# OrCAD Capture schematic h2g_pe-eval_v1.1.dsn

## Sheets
1 Interface-Power: size C; title: H2G PE-Eval PCB; rev: 1.1; company: University of Arkansas (NCREPT); note: 700 W. Research Center Blvd; note: Fayetteville, AR 72701
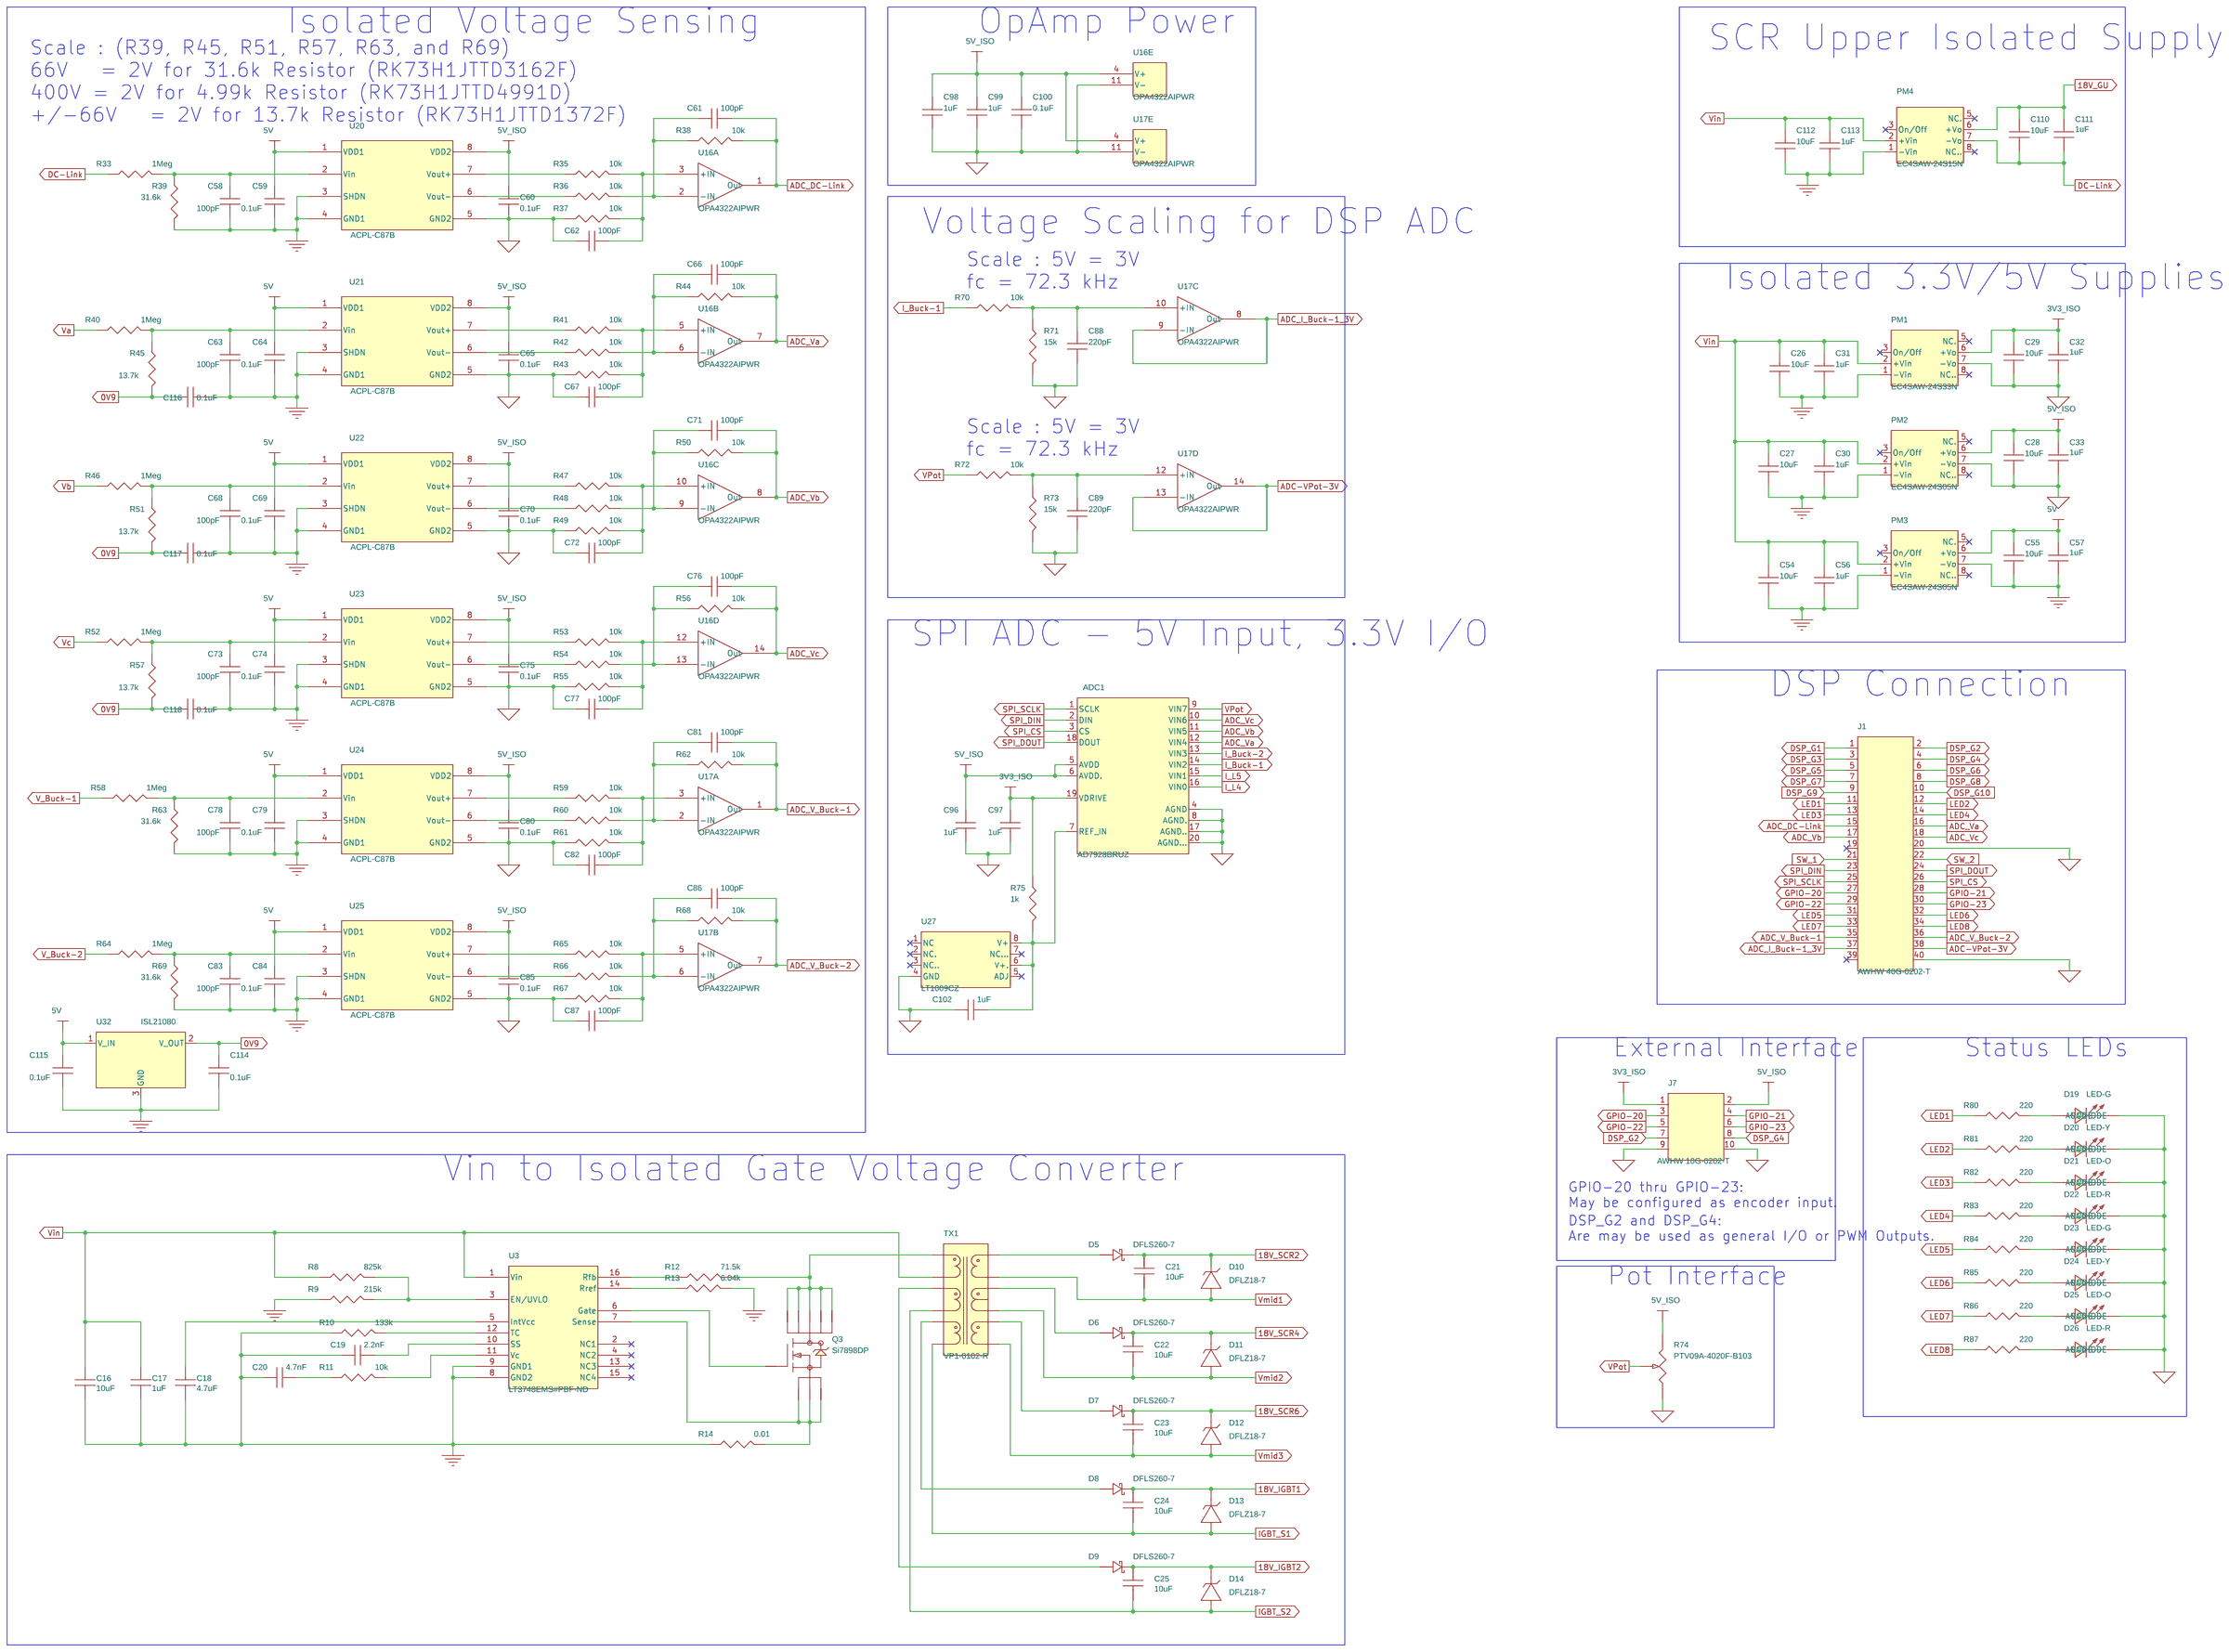
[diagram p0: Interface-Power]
2 Converters: size C
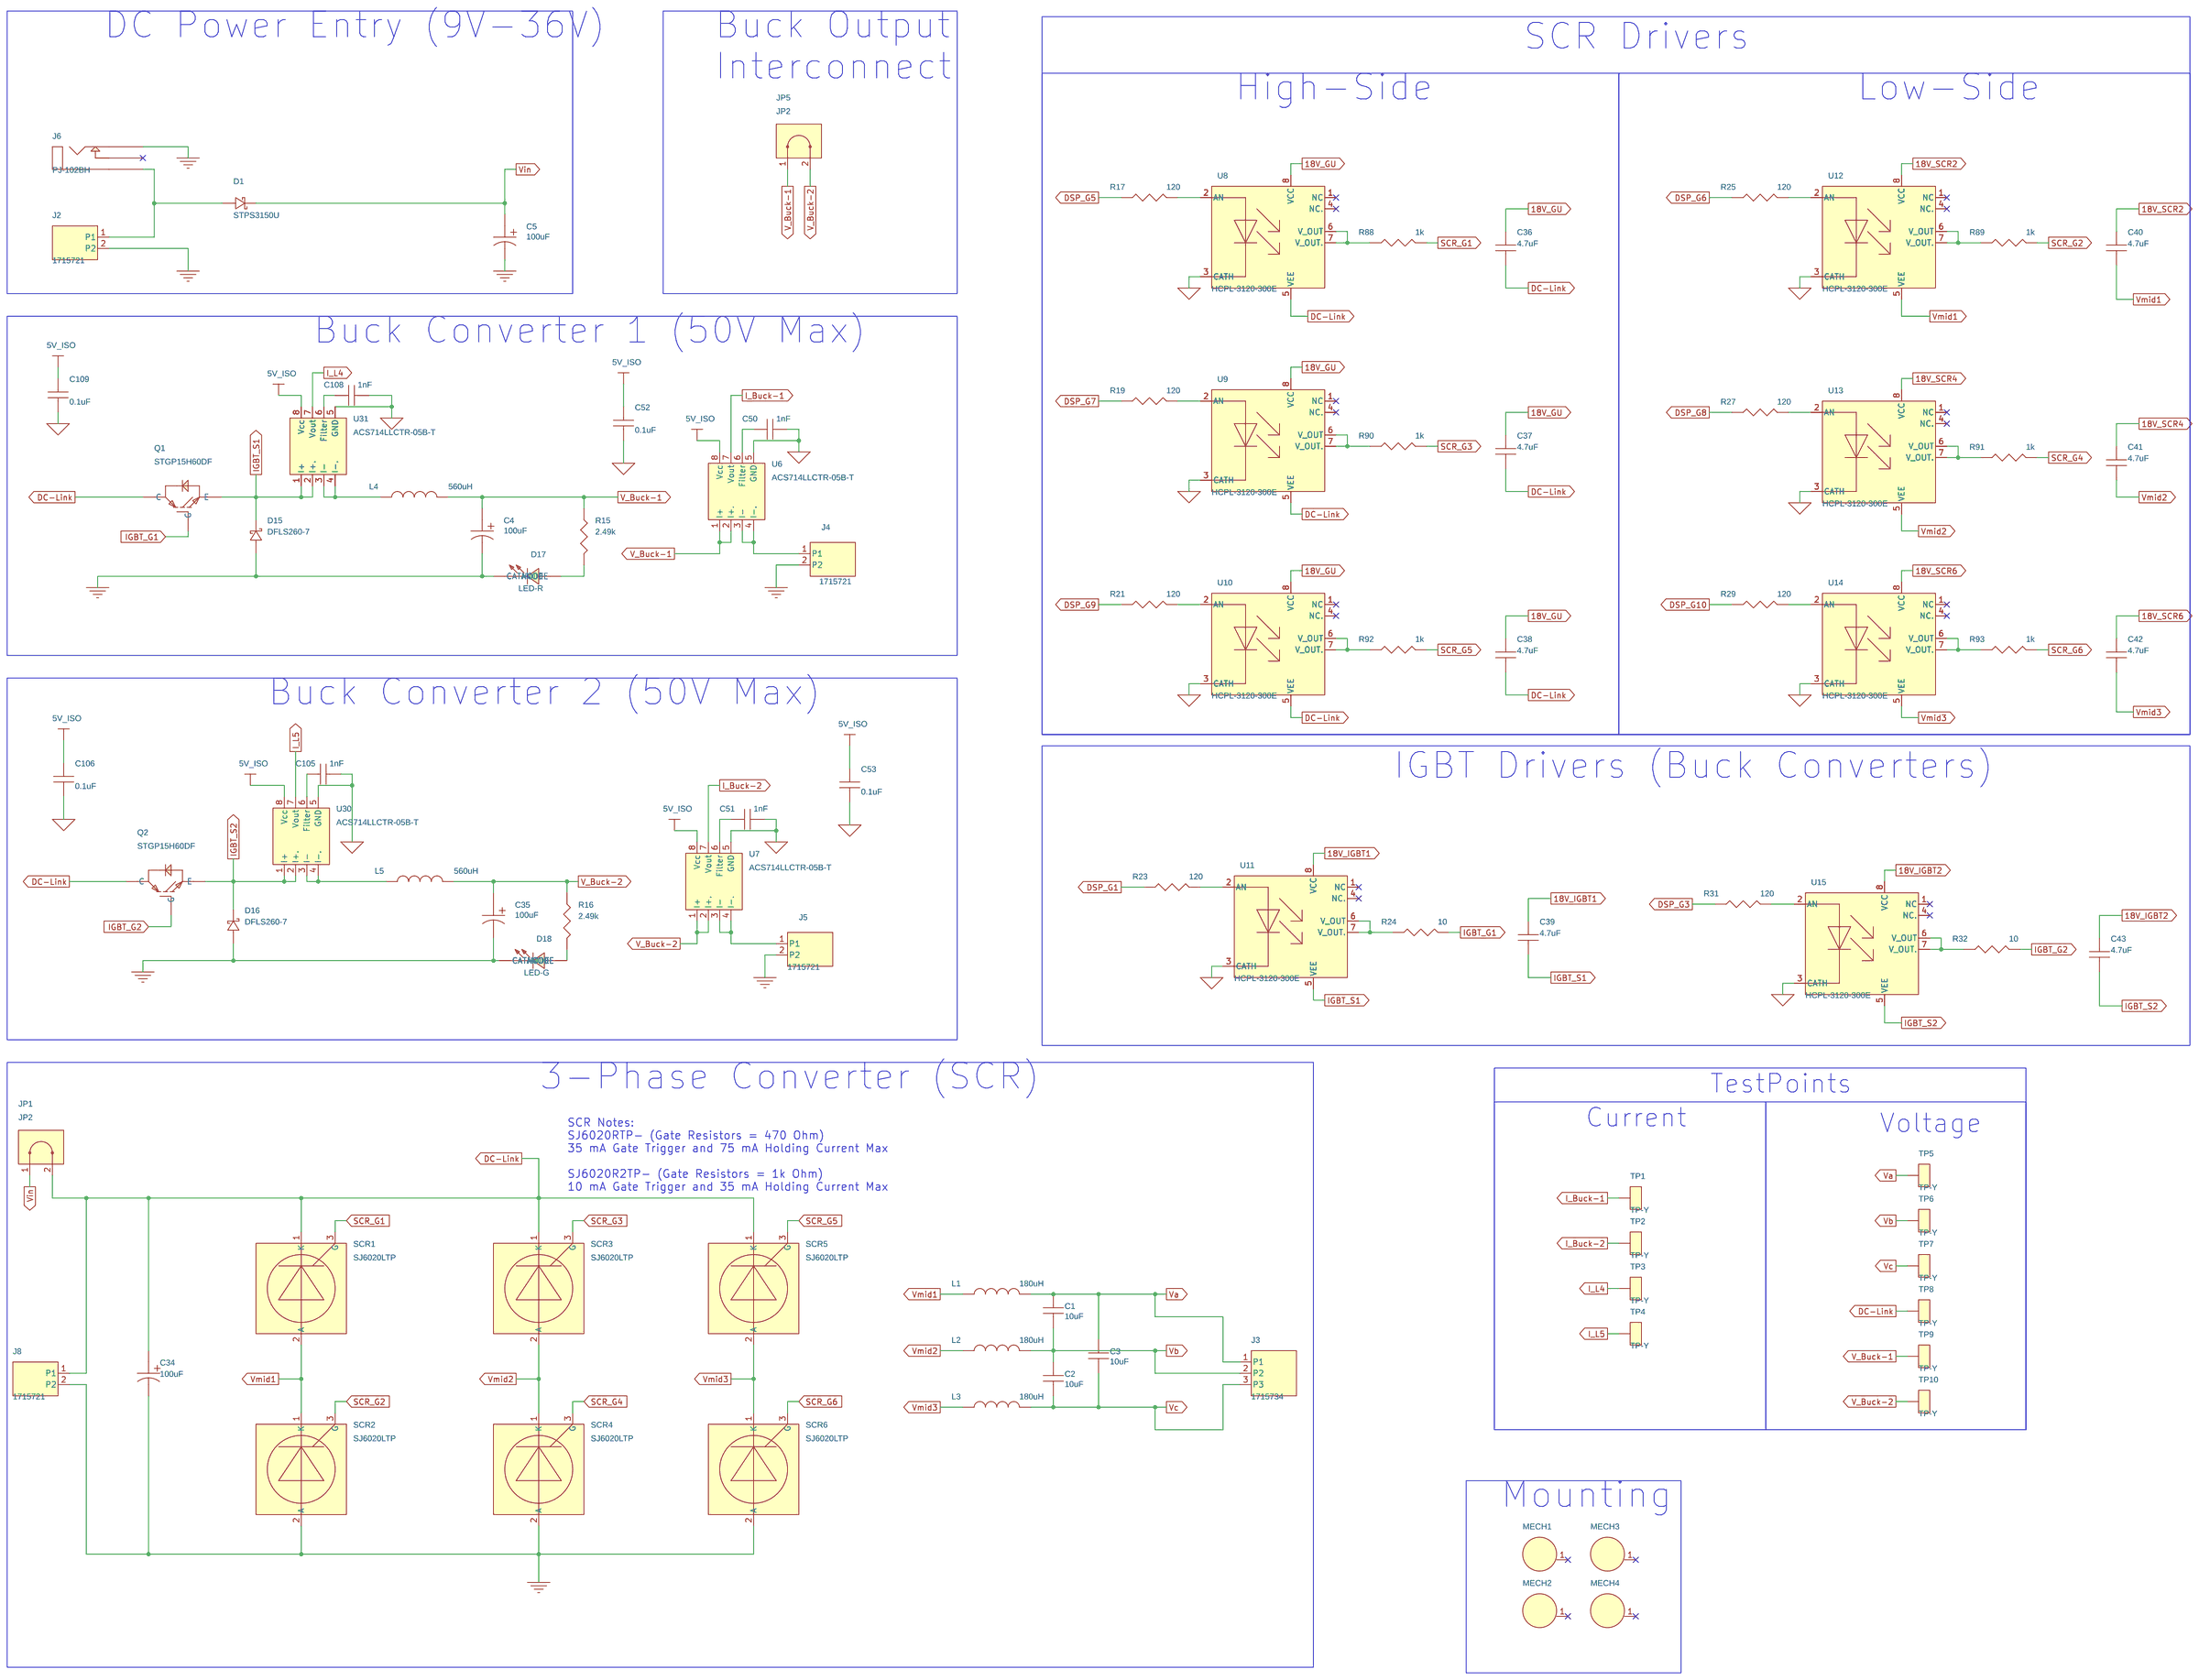
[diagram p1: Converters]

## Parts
sheet Converters
C1  10uF  [ECQ-E2106KFB]
C2  10uF  [ECQ-E2106KFB]
C3  10uF  [ECQ-E2106KFB]
C4  100uF  [UVZ1H101MPD]
C5  100uF  [UVZ1H101MPD]
C34  100uF  [UVZ1H101MPD]
C35  100uF  [UVZ1H101MPD]
C36  4.7uF  [C_1206]
C37  4.7uF  [C_1206]
C38  4.7uF  [C_1206]
C39  4.7uF  [C_1206]
C40  4.7uF  [C_1206]
C41  4.7uF  [C_1206]
C42  4.7uF  [C_1206]
C43  4.7uF  [C_1206]
C50  1nF  [C_0603]
C51  1nF  [C_0603]
C52  0.1uF  [C_0603]
C53  0.1uF  [C_0603]
C105  1nF  [C_0603]
C106  0.1uF  [C_0603]
C108  1nF  [C_0603]
C109  0.1uF  [C_0603]
D1  STPS3150U  [DO-214AA_SMB]
D15  DFLS260-7  [PowerDI-123]
D16  DFLS260-7  [PowerDI-123]
D17  LED-R  [LED_0805-RED]
D18  LED-G  [LED_0805-GREEN]
J2  1715721  [1715721]
J3  1715734  [1715734]
J4  1715721  [1715721]
J5  1715721  [1715721]
J6  PJ-102BH  [DC-PWR_JACK]
J8  1715721  [1715721]
JP1  JP2  [J_1X2]
JP5  JP2  [J_1X2]
L1  180uH  [PCV-2-184-05L]
L2  180uH  [PCV-2-184-05L]
L3  180uH  [PCV-2-184-05L]
L4  560uH  [PCV-2-564-02L]
L5  560uH  [PCV-2-564-02L]
MECH1  Mech_Hole  [4-40_SCREW]
MECH2  Mech_Hole  [4-40_SCREW]
MECH3  Mech_Hole  [4-40_SCREW]
MECH4  Mech_Hole  [4-40_SCREW]
Q1  STGP15H60DF  [TO-220]
Q2  STGP15H60DF  [TO-220]
R15  2.49k  [R_2512]
R16  2.49k  [R_2512]
R17  120  [R_1206]
R19  120  [R_1206]
R21  120  [R_1206]
R23  120  [R_1206]
R24  10  [R_1206]
R25  120  [R_1206]
R27  120  [R_1206]
R29  120  [R_1206]
R31  120  [R_1206]
R32  10  [R_1206]
R88  1k  [R_0805]
R89  1k  [R_0805]
R90  1k  [R_0805]
R91  1k  [R_0805]
R92  1k  [R_0805]
R93  1k  [R_0805]
SCR1  SJ6020LTP  [TO-220]
SCR2  SJ6020LTP  [TO-220]
SCR3  SJ6020LTP  [TO-220]
SCR4  SJ6020LTP  [TO-220]
SCR5  SJ6020LTP  [TO-220]
SCR6  SJ6020LTP  [TO-220]
TP1  TP-Y  [TP-YELLOW]
TP2  TP-Y  [TP-YELLOW]
TP3  TP-Y  [TP-YELLOW]
TP4  TP-Y  [TP-YELLOW]
TP5  TP-Y  [TP-YELLOW]
TP6  TP-Y  [TP-YELLOW]
TP7  TP-Y  [TP-YELLOW]
TP8  TP-Y  [TP-YELLOW]
TP9  TP-Y  [TP-YELLOW]
TP10  TP-Y  [TP-YELLOW]
U6  ACS714LLCTR-05B-T  [8-SOIC]
U7  ACS714LLCTR-05B-T  [8-SOIC]
U8  HCPL-3120-300E  [8-DIP_GW]
U9  HCPL-3120-300E  [8-DIP_GW]
U10  HCPL-3120-300E  [8-DIP_GW]
U11  HCPL-3120-300E  [8-DIP_GW]
U12  HCPL-3120-300E  [8-DIP_GW]
U13  HCPL-3120-300E  [8-DIP_GW]
U14  HCPL-3120-300E  [8-DIP_GW]
U15  HCPL-3120-300E  [8-DIP_GW]
U30  ACS714LLCTR-05B-T  [8-SOIC]
U31  ACS714LLCTR-05B-T  [8-SOIC]
sheet Interface-Power
ADC1  AD7928BRUZ  [20-TSSOP]
C16  10uF  [C_1206]
C17  1uF  [C_0603]
C18  4.7uF  [C_1206]
C19  2.2nF  [C_0603]
C20  4.7nF  [C_0603]
C21  10uF  [C_1206]
C22  10uF  [C_1206]
C23  10uF  [C_1206]
C24  10uF  [C_1206]
C25  10uF  [C_1206]
C26  10uF  [C_1206]
C27  10uF  [C_1206]
C28  10uF  [C_1206]
C29  10uF  [C_1206]
C30  1uF  [C_0603]
C31  1uF  [C_0603]
C32  1uF  [C_0603]
C33  1uF  [C_0603]
C54  10uF  [C_1206]
C55  10uF  [C_1206]
C56  1uF  [C_0603]
C57  1uF  [C_0603]
C58  100pF  [C_0603]
C59  0.1uF  [C_0603]
C60  0.1uF  [C_0603]
C61  100pF  [C_0603]
C62  100pF  [C_0603]
C63  100pF  [C_0603]
C64  0.1uF  [C_0603]
C65  0.1uF  [C_0603]
C66  100pF  [C_0603]
C67  100pF  [C_0603]
C68  100pF  [C_0603]
C69  0.1uF  [C_0603]
C70  0.1uF  [C_0603]
C71  100pF  [C_0603]
C72  100pF  [C_0603]
C73  100pF  [C_0603]
C74  0.1uF  [C_0603]
C75  0.1uF  [C_0603]
C76  100pF  [C_0603]
C77  100pF  [C_0603]
C78  100pF  [C_0603]
C79  0.1uF  [C_0603]
C80  0.1uF  [C_0603]
C81  100pF  [C_0603]
C82  100pF  [C_0603]
C83  100pF  [C_0603]
C84  0.1uF  [C_0603]
C85  0.1uF  [C_0603]
C86  100pF  [C_0603]
C87  100pF  [C_0603]
C88  220pF  [C_0603]
C89  220pF  [C_0603]
C96  1uF  [C_0603]
C97  1uF  [C_0603]
C98  1uF  [C_0603]
C99  1uF  [C_0603]
C100  0.1uF  [C_0603]
C102  1uF  [C_0603]
C110  10uF  [C_1206]
C111  1uF  [C_0603]
C112  10uF  [C_1206]
C113  1uF  [C_0603]
C114  0.1uF  [C_0603]
C115  0.1uF  [C_0603]
C116  0.1uF  [C_0603]
C117  0.1uF  [C_0603]
C118  0.1uF  [C_0603]
D5  DFLS260-7  [PowerDI-123]
D6  DFLS260-7  [PowerDI-123]
D7  DFLS260-7  [PowerDI-123]
D8  DFLS260-7  [PowerDI-123]
D9  DFLS260-7  [PowerDI-123]
D10  DFLZ18-7  [PowerDI-123]
D11  DFLZ18-7  [PowerDI-123]
D12  DFLZ18-7  [PowerDI-123]
D13  DFLZ18-7  [PowerDI-123]
D14  DFLZ18-7  [PowerDI-123]
D19  LED-G  [LED_0805-GREEN]
D20  LED-Y  [LED_0805-YELLOW]
D21  LED-O  [LED_0805-ORANGE]
D22  LED-R  [LED_0805-RED]
D23  LED-G  [LED_0805-GREEN]
D24  LED-Y  [LED_0805-YELLOW]
D25  LED-O  [LED_0805-ORANGE]
D26  LED-R  [LED_0805-RED]
J1  AWHW 40G-0202-T  [40-IDC-M]
J7  AWHW 10G-0202-T  [10-IDC-M]
PM1  EC4SAW-24S33N  [SIP-8]
PM2  EC4SAW-24S05N  [SIP-8]
PM3  EC4SAW-24S05N  [SIP-8]
PM4  EC4SAW-24S15N  [SIP-8]
Q3  Si7898DP  [SO-8_PP]
R8  825k  [R_0603]
R9  215k  [R_0603]
R10  133k  [R_0603]
R11  10k  [R_0603]
R12  71.5k  [R_0603]
R13  6.04k  [R_0603]
R14  0.01  [R_1206]
R33  1Meg  [R_1206]
R35  10k  [R_0603]
R36  10k  [R_0603]
R37  10k  [R_0603]
R38  10k  [R_0603]
R39  31.6k  [R_0805]
R40  1Meg  [R_1206]
R41  10k  [R_0603]
R42  10k  [R_0603]
R43  10k  [R_0603]
R44  10k  [R_0603]
R45  13.7k  [R_0603]
R46  1Meg  [R_1206]
R47  10k  [R_0603]
R48  10k  [R_0603]
R49  10k  [R_0603]
R50  10k  [R_0603]
R51  13.7k  [R_0603]
R52  1Meg  [R_1206]
R53  10k  [R_0603]
R54  10k  [R_0603]
R55  10k  [R_0603]
R56  10k  [R_0603]
R57  13.7k  [R_0603]
R58  1Meg  [R_1206]
R59  10k  [R_0603]
R60  10k  [R_0603]
R61  10k  [R_0603]
R62  10k  [R_0603]
R63  31.6k  [R_0805]
R64  1Meg  [R_1206]
R65  10k  [R_0603]
R66  10k  [R_0603]
R67  10k  [R_0603]
R68  10k  [R_0603]
R69  31.6k  [R_0805]
R70  10k  [R_0603]
R71  15k  [R_0603]
R72  10k  [R_0603]
R73  15k  [R_0603]
R74  PTV09A-4020F-B103  [9MM_POT]
R75  1k  [R_0805]
R80  220  [R_0805]
R81  220  [R_0805]
R82  220  [R_0805]
R83  220  [R_0805]
R84  220  [R_0805]
R85  220  [R_0805]
R86  220  [R_0805]
R87  220  [R_0805]
TX1  VP1-0102-R  [TX-VP1]
U3  LT3748EMS#PBF-ND  [16-MSOP]
U16  OPA4322AIPWR  [OPA4332_14-TSSOP]  (sections A,B,C,D,E)
U17  OPA4322AIPWR  [OPA4332_14-TSSOP]  (sections A,B,C,D,E)
U20  ACPL-C87B  [ACPL-C87X]
U21  ACPL-C87B  [ACPL-C87X]
U22  ACPL-C87B  [ACPL-C87X]
U23  ACPL-C87B  [ACPL-C87X]
U24  ACPL-C87B  [ACPL-C87X]
U25  ACPL-C87B  [ACPL-C87X]
U27  LT1009CZ  [8-MSOP]
U32  ISL21080  [SOT_23-3]

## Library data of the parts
C1-C3 = CAP_NP: Film Capacitor, 10uF, 250Vdc; Manufacturer: Panasonic; Part_Number: Cap-00019; Tolerance: 10%; Voltage: 250V; Datasheet: Panasonic-ABD0000C179-947645.pdf
C4 C5 C34 C35 = CAP_P: Electrolytic Capacitor (50V/100uF); Manufacturer: Nichicon; Part_Number: Cap-00020; Voltage: 50V; Datasheet: Nicicon-e-uvz-880014.pdf
C18 C36-C43 = CAP_NP: 4.7µF ±10% 50V X7R MLCC; Manufacturer: TDK; Manufacturer_Part_Number: C3216X7R1H475K160AC; Part_Number: Cap-00015; Tolerance: 10%; Voltage: 50V; Datasheet: TDK-mlcc_commercial_general_en.pdf
C50 C51 C105 C108 = CAP_NP: 1nF ±10% 100V X7R MLCC; Manufacturer: TDK; Manufacturer_Part_Number: C1608X7R2A102K080AA; Part_Number: Cap-00005; Tolerance: 10%; Voltage: 100V; Datasheet: TDK-mlcc_commercial_general_en.pdf
C52 C53 C59 C60 C64 C65 C69 C70 C74 C75 C79 C80 C84 C85 C100 C106 C109 C114-C118 = CAP_NP: 0.1µF ±10% 50V X7R MLCC; Manufacturer: TDK; Manufacturer_Part_Number: C1608X7R1H104K080AA; Part_Number: Cap-00001; Tolerance: 10%; Voltage: 50V; Datasheet: TDK-mlcc_commercial_general_en.pdf
D1 = D-Schottky: Schottky Diode 3A/150V; Manufacturer: ST; Part_Number: D-00001; STEP_Model: Diode SMA.stp; Datasheet: ST-en.CD00003323.pdf
D5-D9 D15 D16 = D-Schottky: Schottky Diode 2A/60V; Manufacturer: Diodes Incorporated; Part_Number: D-00005; STEP_Model: POWERDI-123.stp; Datasheet: DiodesInc-ds31476-56424.pdf
D17 D22 D26 = LED: LED, 0805, Red, VF= 1.8V; Manufacturer: OSRAM; Manufacturer_Part_Number: LH R974-LP-1; Part_Number: D-00007; STEP_Model: LED_0805-Red.stp; Datasheet: OSRAM-LHR974-CHIPLED0805-318659.pdf
D18 D19 D23 = LED: LED, 0805, Green, VF= 2.2V; Manufacturer: OSRAM; Manufacturer_Part_Number: LG R971-KN-1; Part_Number: D-00008; STEP_Model: LED_0805-Green.stp; Datasheet: OSRAM-LGR971-CHIPLED-0805-318376.pdf
J2 J4 J5 J8 = Connector-2: PCB Terminal Block, 2-position, 90 degrees, 5.08mm; Manufacturer: Phoenix Contact; Part_Number: Con-00006; Rating: 17.5A; STEP_Model: 1715721.stp; Voltage: 400V; Datasheet: PhoenixContact-1715734.pdf
J3 = Connector-3: PCB Terminal Block, 3-position, 90 degrees, 5.08mm; Manufacturer: Phoenix Contact; Part_Number: Con-00007; Rating: 17.5A; STEP_Model: 1715734.stp; Voltage: 400V; Datasheet: PhoenixContact-1715734.pdf
J6 = DC-Jack_3: DC Power Jack, 2.5mm Center Pin, TH; Manufacturer: CUI; Part_Number: Con-00017; STEP_Model: pj-102bh.stp; Datasheet: CUI-PJ-102BH-524153.pdf
JP1 JP5 = JP2: Male, TH, Straight, 2-Pos, 0.1" Pitch; Manufacturer: Various; Manufacturer_Part_Number: PRT-00116; Part_Number: JP-00001
L1-L3 = Ind: 180uH, 4.0A, PCV-2; Manufacturer: CoilCraft; Part_Number: Ind-00009; Rating: 4A; Tolerance: 10%; Datasheet: CoilCraft-pcv.pdf
L4 L5 = Ind: 560uH, 2.6A, PCV-2; Manufacturer: CoilCraft; Part_Number: Ind-00010; Rating: 2.6A; Tolerance: 10%; Datasheet: CoilCraft-pcv.pdf
MECH1-MECH4 = Mech_Hole: Mounting Hole for 4-40 Screw, 0.125"; Part_Number: Con-00005
Q1 Q2 = IGBT_TO220: IGBT Trench gate 600V 15A; Manufacturer: STMicroelectrionics; Part_Number: Q-00004; Datasheet: ST-stgb15h60df-955853.pdf
R15 R16 = R-Standard: 2.49k Ohm, 1%, 2512; Manufacturer: KOA Speer; Manufacturer_Part_Number: RK73H3ATTE2491F; Part_Number: Res-00044; Rating: 1W; Tolerance: 1%; Datasheet: KOA-RK73H-5715.pdf
R17 R19 R21 R23 R25 R27 R29 R31 = R-Standard: 120 Ohm, 1%, 1206; Manufacturer: KOA Speer; Manufacturer_Part_Number: RK73H2BTTD1200F; Part_Number: Res-00041; Rating: 0.25W; Tolerance: 1%; Datasheet: KOA-RK73H-5715.pdf
R24 R32 = R-Standard: 10 Ohm, 1%, 1206; Manufacturer: KOA Speer; Manufacturer_Part_Number: RK73H2BTTD10R0F; Part_Number: Res-00008; Rating: 0.25W; Tolerance: 1%; Datasheet: KOA-RK73H-5715.pdf
R88-R93 = R-Standard: 1k Ohm, 1%, 0805; Manufacturer: KOA Speer; Manufacturer_Part_Number: RK73H2ATTD1001F; Part_Number: Res-00012; Tolerance: 1%; Datasheet: KOA-RK73H-5715.pdf
SCR1-SCR6 = SJ6020LTP: SCRs 20A High Temp Thyristor; Manufacturer: Littelfuse; Part_Number: Q-00011; Datasheet: Littelfuse_Thyristor_SJxx20xx_Datasheet.pdf-1314442
TP1-TP10 = TP: PCB Test Point TH Yellow; Manufacturer: Keystone Electronics; Manufacturer_Part_Number: 5004; Part_Number: TP-00005; Datasheet: Keystone-000-5004-741320.pdf
U6 U7 U30 U31 = ACS714: Hall Effect Sensor, 5A AC/DC,185mV/A; Manufacturer: Allegro; Part_Number: IC-00016; Tolerance: 1.50%; Datasheet: Allegro-ACS714-Datasheet.pdf
U8-U15 = HCPL-3120: 2.5 Amp  IGBT Gate Drive, Optocoupler, Gullwing; Manufacturer: Avago; Part_Number: IC-00022; STEP_Model: 8-pin-DIP_GW_HCPL-300E.stp; Datasheet: Avago-AV02-0161EN_DS_HCPL-3120_2016-03-21.pdf
ADC1 = AD7928BRUZ: ADC 8-Ch, 12-Bit, 1MSPS; Manufacturer: Analog Devices; Part_Number: IC-00023; STEP_Model: TSSOP65P640X120-20N.stp; Datasheet: AnalogDevices-AD7908_7918_7928-877555.pdf
C16 C21-C29 C54 C55 C110 C112 = CAP_NP: 10µF ±20% 35V X7R MLCC; Manufacturer: TDK; Manufacturer_Part_Number: C3216X7R1V106M160AC; Part_Number: Cap-00002; Tolerance: 20%; Voltage: 35V; Datasheet: TDK-mlcc_commercial_general_en.pdf
C17 C30-C33 C56 C57 C96-C99 C102 C111 C113 = CAP_NP: 1µF ±10% 35V X7R MLCC; Manufacturer: TDK; Manufacturer_Part_Number: C1608X7R1V105K080AC; Part_Number: Cap-00008; Tolerance: 10%; Voltage: 35V; Datasheet: TDK-mlcc_commercial_general_en.pdf
C19 = CAP_NP: 2.2nF ±10% 100V X7R MLCC; Manufacturer: TDK; Manufacturer_Part_Number: C1608X7R2A222K080AA; Part_Number: Cap-00016; Tolerance: 10%; Voltage: 100V; Datasheet: TDK-mlcc_commercial_general_en.pdf
C20 = CAP_NP: 4.7nF ±10% 100V X7R MLCC; Manufacturer: TDK; Manufacturer_Part_Number: C1608X7R2A472K080AA; Part_Number: Cap-00017; Tolerance: 10%; Voltage: 100V; Datasheet: TDK-mlcc_commercial_general_en.pdf
C58 C61-C63 C66-C68 C71-C73 C76-C78 C81-C83 C86 C87 = CAP_NP: 100pF ±10% 100V C0G MLCC; Manufacturer: TDK; Manufacturer_Part_Number: C1608C0G2A101K080AA; Part_Number: Cap-00013; Tolerance: 10%; Voltage: 100V; Datasheet: TDK-mlcc_commercial_general_en.pdf
C88 C89 = CAP_NP: 0.22nF ±5% 100V C0G MLCC; Manufacturer: TDK; Manufacturer_Part_Number: C1608C0G2A221J080AA; Part_Number: Cap-00018; Tolerance: 5%; Voltage: 100V; Datasheet: TDK-mlcc_commercial_general_en.pdf
D10-D14 = D-Zener: Zener Diode 18V 1W; Manufacturer: Diodes Incorporated; Part_Number: D-00003; STEP_Model: POWERDI-123.stp; Tolerance: 6%; Datasheet: DiodesInc-ds30464.pdf
D20 D24 = LED: LED, 0805, Yellow, VF= 2.0V; Manufacturer: OSRAM; Manufacturer_Part_Number: LY R976-PS-36; Part_Number: D-00009; STEP_Model: LED_0805-Yellow.stp; Datasheet: OSRAM-LYR976-CHIPLED0805-318976.pdf
D21 D25 = LED: LED, 0805, Orange, VF= 2.0V; Manufacturer: OSRAM; Manufacturer_Part_Number: LO R976-PS-1; Part_Number: D-00010; STEP_Model: LED_0805-Orange.stp; Datasheet: OSRAM-LOR976-CHIPLED0805-318582.pdf
J1 = Header_2x20: 40-POS Header, Shrouded, 0.100", TH; Manufacturer: Assmann; Part_Number: Con-00015; STEP_Model: HDB-40.stp; User_Field1: SBH11-PBPC-D20-ST-BK; Datasheet: Assmann-AWHW-xxG-0x02-T.pdf
J7 = Header_2x5: 10-POS Header, Shrouded, 0.100", TH; Manufacturer: Assmann; Part_Number: Con-00013; STEP_Model: HDB-10.stp; User_Field1: SBH11-PBPC-D05-ST-BK; Datasheet: Assmann-AWHW-xxG-0x02-T.pdf
PM1 = EC4SA: Isolated DC/DC Converters 5 Watt, 9-36 Vin, 3.3 Vout; Manufacturer: Cincon; Part_Number: PS-00001; STEP_Model: PwrMod-SIP8.stp; Tolerance: 1.50%; Datasheet: CINCON-EC4SAW V10-557886.pdf
PM2 PM3 = EC4SA: Isolated DC/DC Converters 6 Watt, 9-36 Vin, 5 Vout; Manufacturer: Cincon; Part_Number: PS-00002; STEP_Model: PwrMod-SIP8.stp; Tolerance: 1.50%; Datasheet: CINCON-EC4SAW V10-557886.pdf
PM4 = EC4SA: Isolated DC/DC Converters 6 Watt, 9-36 Vin, 15 Vout; Manufacturer: Cincon; Part_Number: PS-00003; Tolerance: 1.50%; Datasheet: CINCON-EC4SAW V10-557886.pdf
Q3 = N-FET_Si7898DP: Si N-Chan MOSFET 150V/3A; Manufacturer: Vishay; Manufacturer_Part_Number: SI7898DP-T1-E3; Part_Number: Q-00003; Datasheet: Vishay-71873.pdf
R8 = R-Standard: 825k Ohm, 1%, 0603; Manufacturer: KOA Speer; Manufacturer_Part_Number: RK73H1JTTD8253F; Part_Number: Res-00025; Rating: 0.1W; Tolerance: 1%; Datasheet: KOA-RK73H-5715.pdf
R9 = R-Standard: 215k Ohm, 1%, 0603; Manufacturer: KOA Speer; Manufacturer_Part_Number: RK73H1JTTD2153F; Part_Number: Res-00057; Rating: 0.1W; Tolerance: 1%; Datasheet: KOA-RK73H-5715.pdf
R10 = R-Standard: 133k Ohm, 1%, 0603; Manufacturer: KOA Speer; Manufacturer_Part_Number: RK73H1JTTD1333F; Part_Number: Res-00030; Rating: 0.1W; Tolerance: 1%; Datasheet: KOA-RK73H-5715.pdf
R11 R35-R38 R41-R44 R47-R50 R53-R56 R59-R62 R65-R68 R70 R72 = R-Standard: 10k Ohm, 1%, 0603; Manufacturer: KOA Speer; Manufacturer_Part_Number: RK73H1JTTD1002F; Part_Number: Res-00031; Rating: 0.1W; Tolerance: 1%; Datasheet: KOA-RK73H-5715.pdf
R12 = R-Standard: 71.5k Ohm, 1%, 0603; Manufacturer: KOA Speer; Manufacturer_Part_Number: RK73H1JTTD7152F; Part_Number: Res-00027; Rating: 0.1W; Tolerance: 1%; Datasheet: KOA-RK73H-5715.pdf
R13 = R-Standard: 6.04k Ohm, 1%, 0603; Manufacturer: KOA Speer; Manufacturer_Part_Number: RK73H1JTTD6041F; Part_Number: Res-00029; Rating: 0.1W; Tolerance: 1%; Datasheet: KOA-RK73H-5715.pdf
R14 = R-Standard: 10m Ohm, 1%, 1206, Current Sense Res; Manufacturer: KOA Speer; Manufacturer_Part_Number: UR73VD2BTTD10L0F; Part_Number: Res-00033; Rating: 0.5W; Tolerance: 1%; Datasheet: KOA-UR73V-770279.pdf
R33 R40 R46 R52 R58 R64 = R-Standard: 1M Ohm, 1%,1206; Manufacturer: KOA Speer; Manufacturer_Part_Number: RK73H2BTTD1004F; Part_Number: Res-00034; Tolerance: 1%; Datasheet: KOA-RK73H-5715.pdf
R39 R63 R69 = R-Standard: 31.6k Ohm, 1%, 0603; Manufacturer: KOA Speer; Manufacturer_Part_Number: RK73H1JTTD3162F; Part_Number: Res-00022; Rating: 0.1W; Tolerance: 1%; Datasheet: KOA-RK73H-5715.pdf
R45 R51 R57 = R-Standard: 13.7k Ohm, 1%, 0603; Manufacturer: KOA Speer; Manufacturer_Part_Number: RK73H1JTTD1372F; Part_Number: TMP-372; Tolerance: 1%; Datasheet: KOA-RK73H-5715.pdf
R71 R73 = R-Standard: 15k Ohm, 1%, 0603; Manufacturer: KOA Speer; Manufacturer_Part_Number: RK73H1JTTD1502F; Part_Number: Res-00037; Rating: 0.1W; Tolerance: 1%; Datasheet: KOA-RK73H-5715.pdf
R74 = R-POT: Potentiometer 10k Linear, 6mm Shaft,TH; Manufacturer: Bourns; Part_Number: Res-00043; Tolerance: 20%; Datasheet: Bourns-tv09-777818.pdf
R75 = R-Standard: 1k Ohm, 1%, 0805; Manufacturer: KOA Speer; Manufacturer_Part_Number: RK73H2ATTD1001F; Part_Number: Res-00012; Rating: 0.125W; Tolerance: 1%; Datasheet: KOA-RK73H-5715.pdf
R80-R87 = R-Standard: 220 Ohm, 1%, 0805; Manufacturer: KOA Speer; Manufacturer_Part_Number: RK73H2ATTD2200F; Part_Number: Res-00017; Rating: 0.125W; Tolerance: 1%; Datasheet: KOA-RK73H-5715.pdf
TX1 = TX_VP1-0102-R: 6.5µH, 0.8A, 6-Winding XFMR, VTP1, 20%; Manufacturer: Eaton; Part_Number: XFRM-00002; Tolerance: 20%; Datasheet: Eaton-BUS_Elx_PM_4301_VERSA_PAC.pdf
U3 = LT3748EMS#PBF-ND: Flyback Controller (Used with VP1 Arrays); Manufacturer: Linear Tech; Part_Number: IC-00010; STEP_Model: MSOP-16_MSEP16-12.stp; Datasheet: LT-3748fb.pdf
U16 U17 = OPA4322AIPWR: Quad OpAmp, 20 MHz; Manufacturer: TI; Part_Number: IC-00012; STEP_Model: TSSOP14.stp; User_Field1: https://www.google.com/; Datasheet: TI-opa4322.pdf
U20-U25 = ACPL-C87B: Isolation OpAmp, 100 kHz; Manufacturer: Avago; Manufacturer_Part_Number: ACPL-C87B-000E; Part_Number: IC-00011; STEP_Model: SOIC08 wide.stp; Datasheet: Avago-AV02-3563EN_DS_ACPL-C87x_04Mar2013.pdf
U27 = LT1009CZ: 2.5V Voltage Reference, ±0.2%, SMD; Manufacturer: Linear Tech; Manufacturer_Part_Number: LT1009CMS8#PBF; Part_Number: IC-00024; STEP_Model: MSOP8.stp; Tolerance: 0.20%; Datasheet: LinearTech-1009ff.pdf
U32 = ISL21080: 0.9V Voltage Reference, ±0.7%; Manufacturer: Intersil; Manufacturer_Part_Number: ISL21080DIH309Z-TK; Part_Number: IC-00014; Tolerance: 0.70%; Datasheet: Intersil-isl21080.pdf

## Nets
0V9: C114.1 C116.1 C117.1 C118.1 R45.2 R51.2 R57.2 U32.2(V_OUT)
3V3_Iso: ADC1.19(VDRIVE) C29.1 C32.1 C97.1 J7.1 PM1.6(+Vo) R75.1
5V: C55.1 C57.1 C59.1 C64.1 C69.1 C74.1 C79.1 C84.1 C115.1 PM3.6(+Vo) U20.1(VDD1) U21.1(VDD1) U22.1(VDD1) U23.1(VDD1) U24.1(VDD1) U25.1(VDD1) U32.1(V_IN)
5V_Iso: ADC1.5(AVDD) ADC1.6(AVDD.) C28.1 C33.1 C52.1 C53.1 C60.1 C65.1 C70.1 C75.1 C80.1 C85.1 C96.1 C98.1 C99.1 C100.1 C106.1 C109.1 J7.2 PM2.6(+Vo) R74.3(B) U6.8(Vcc) U7.8(Vcc) U16.4(V+) U17.4(V+) U20.8(VDD2) U21.8(VDD2) U22.8(VDD2) U23.8(VDD2) U24.8(VDD2) U25.8(VDD2) U30.8(Vcc) U31.8(Vcc)
18V_GU: C36.1 C37.1 C38.1 C110.1 C111.1 PM4.6(+Vo) U8.8(VCC) U9.8(VCC) U10.8(VCC)
18V_IGBT1: C24.1 C39.1 D8.1 D13.1 U11.8(VCC)
18V_IGBT2: C25.1 C43.1 D9.1 D14.1 U15.8(VCC)
18V_SCR2: C21.1 C40.1 D5.1 D10.1 U12.8(VCC)
18V_SCR4: C22.1 C41.1 D6.1 D11.1 U13.8(VCC)
18V_SCR6: C23.1 C42.1 D7.1 D12.1 U14.8(VCC)
GND: C4.2 C5.2 C16.2 C17.2 C18.2 C19.1 C20.1 C26.2 C27.2 C30.2 C31.2 C34.2 C35.2 C54.2 C55.2 C56.2 C57.2 C58.2 C59.2 C63.2 C64.2 C68.2 C69.2 C73.2 C74.2 C78.2 C79.2 C83.2 C84.2 C112.2 C113.2 C114.2 C115.2 C116.2 C117.2 C118.2 D15.2 D16.2 D17.1(CATHODE) D18.1(CATHODE) J2.2(P2) J4.2(P2) J5.2(P2) J6.2 J8.2(P2) PM1.1(-Vin) PM2.1(-Vin) PM3.1(-Vin) PM3.7(-Vo) PM4.1(-Vin) R9.1 R10.1 R13.2 R14.1 R39.2 R63.2 R69.2 SCR2.2(A) SCR4.2(A) SCR6.2(A) U3.8(GND2) U3.9(GND1) U20.3(SHDN) U20.4(GND1) U21.3(SHDN) U21.4(GND1) U22.3(SHDN) U22.4(GND1) U23.3(SHDN) U23.4(GND1) U24.3(SHDN) U24.4(GND1) U25.3(SHDN) U25.4(GND1) U32.3(GND)
GND_SIGNAL: ADC1.4(AGND) ADC1.8(AGND.) ADC1.17(AGND..) ADC1.20(AGND...) C28.2 C29.2 C32.2 C33.2 C50.2 C51.2 C52.2 C53.2 C60.2 C62.1 C65.2 C67.1 C70.2 C72.1 C75.2 C77.1 C80.2 C82.1 C85.2 C87.1 C88.2 C89.2 C96.2 C97.2 C98.2 C99.2 C100.2 C102.1 C105.2 C106.2 C108.2 C109.2 D19.1(CATHODE) D20.1(CATHODE) D21.1(CATHODE) D22.1(CATHODE) D23.1(CATHODE) D24.1(CATHODE) D25.1(CATHODE) D26.1(CATHODE) J1.20 J1.40 J7.9 J7.10 PM1.7(-Vo) PM2.7(-Vo) R37.1 R43.1 R49.1 R55.1 R61.1 R67.1 R71.2 R73.2 R74.1(A) U6.5(GND) U7.5(GND) U8.3(CATH) U9.3(CATH) U10.3(CATH) U11.3(CATH) U12.3(CATH) U13.3(CATH) U14.3(CATH) U15.3(CATH) U16.11(V-) U17.11(V-) U20.5(GND2) U21.5(GND2) U22.5(GND2) U23.5(GND2) U24.5(GND2) U25.5(GND2) U27.4(GND) U30.5(GND) U31.5(GND)
Vin: C5.1 C16.1 C17.1 C26.1 C27.1 C30.1 C31.1 C54.1 C56.1 C112.1 C113.1 D1.1 JP1.1 PM1.2(+Vin) PM2.2(+Vin) PM3.2(+Vin) PM4.2(+Vin) R8.1 TX1.1 U3.1(Vin)
ADC-VPot-3V: J1.38 U17.13(-IN) U17.14(Out)
ADC_DC-Link: C61.2 J1.15 R38.2 U16.1(Out)
ADC_I_Buck-1_3V: J1.37 U17.8(Out) U17.9(-IN)
ADC_V_Buck-1: C81.2 J1.35 R62.2 U17.1(Out)
ADC_V_Buck-2: C86.2 J1.36 R68.2 U17.7(Out)
ADC_Va: ADC1.12(VIN4) C66.2 J1.16 R44.2 U16.7(Out)
ADC_Vb: ADC1.11(VIN5) C71.2 J1.17 R50.2 U16.8(Out)
ADC_Vc: ADC1.10(VIN6) C76.2 J1.18 R56.2 U16.14(Out)
DC-Link: C34.1 C36.2 C37.2 C38.2 C110.2 C111.2 J8.1(P1) JP1.2 PM4.7(-Vo) Q1.2(C) Q2.2(C) R33.1 SCR1.1(K) SCR3.1(K) SCR5.1(K) TP8.1 U8.5(VEE) U9.5(VEE) U10.5(VEE)
DSP_G1: J1.1 R23.1
DSP_G2: J1.2 J7.7
DSP_G3: J1.3 R31.1
DSP_G4: J1.4 J7.8
DSP_G5: J1.5 R17.1
DSP_G6: J1.6 R25.1
DSP_G7: J1.7 R19.1
DSP_G8: J1.8 R27.1
DSP_G9: J1.9 R21.1
DSP_G10: J1.10 R29.1
GPIO-20: J1.27 J7.3
GPIO-21: J1.28 J7.4
GPIO-22: J1.29 J7.5
GPIO-23: J1.30 J7.6
I_Buck-1: ADC1.14(VIN2) R70.1 TP1.1 U6.7(Vout)
I_Buck-2: ADC1.13(VIN3) TP2.1 U7.7(Vout)
I_L4: ADC1.16(VIN0) TP3.1 U31.7(Vout)
I_L5: ADC1.15(VIN1) TP4.1 U30.7(Vout)
IGBT_G1: Q1.1(G) R24.2
IGBT_G2: Q2.1(G) R32.2
IGBT_S1: C24.2 C39.2 D13.2 D15.1 Q1.3(E) TX1.3 U11.5(VEE) U31.1(I+) U31.2(I+.)
IGBT_S2: C25.2 C43.2 D14.2 D16.1 Q2.3(E) TX1.2 U15.5(VEE) U30.1(I+) U30.2(I+.)
LED1: J1.11 R80.1
LED2: J1.12 R81.1
LED3: J1.13 R82.1
LED4: J1.14 R83.1
LED5: J1.31 R84.1
LED6: J1.32 R85.1
LED7: J1.33 R86.1
LED8: J1.34 R87.1
SCR_G1: R88.2 SCR1.3(G)
SCR_G2: R89.2 SCR2.3(G)
SCR_G3: R90.2 SCR3.3(G)
SCR_G4: R91.2 SCR4.3(G)
SCR_G5: R92.2 SCR5.3(G)
SCR_G6: R93.2 SCR6.3(G)
SPI_CS: ADC1.3(CS) J1.26
SPI_DIN: ADC1.2(DIN) J1.23
SPI_DOUT: ADC1.18(DOUT) J1.24
SPI_SCLK: ADC1.1(SCLK) J1.25
SW_1: J1.21
SW_2: J1.22
V_Buck-1: C4.1 JP5.1 L4.2 R15.1 R58.1 TP9.1 U6.1(I+) U6.2(I+.)
V_Buck-2: C35.1 JP5.2 L5.2 R16.1 R64.1 TP10.1 U7.1(I+) U7.2(I+.)
Va: C1.1 C3.1 J3.1(P1) L1.2 R40.1 TP5.1
Vb: C1.2 C2.1 J3.2(P2) L2.2 R46.1 TP6.1
Vc: C2.2 C3.2 J3.3(P3) L3.2 R52.1 TP7.1
Vmid1: C21.2 C40.2 D10.2 L1.1 SCR1.2(A) SCR2.1(K) TX1.7 U12.5(VEE)
Vmid2: C22.2 C41.2 D11.2 L2.1 SCR3.2(A) SCR4.1(K) TX1.8 U13.5(VEE)
Vmid3: C23.2 C42.2 D12.2 L3.1 SCR5.2(A) SCR6.1(K) TX1.9 U14.5(VEE)
VPot: ADC1.9(VIN7) R72.1 R74.2(WIPER)
N07970: R8.2 R9.2 U3.3(EN/UVLO)
N08403: C18.1 U3.5(IntVcc)
N08410: R10.2 U3.12(TC)
N08443: C19.2 U3.10(SS)
N08455: R11.2 U3.11(Vc)
N08467: C20.2 R11.1
N09759: Q3.1(S1) Q3.2(S2) Q3.3(S3) R14.2 U3.7(Sense)
N09873: Q3.5(D1) Q3.6(D2) Q3.7(D3) Q3.8(D4) Q3.9(D_EP) R12.2 TX1.4
N10901: Q3.4(G) U3.6(Gate)
N10913: R12.1 U3.16(Rfb)
N10917: R13.1 U3.14(Rref)
N11491: D7.2 TX1.12
N11495: D6.2 TX1.11
N11499: D5.2 TX1.10
N11507: D8.2 TX1.6
N11532: D9.2 TX1.5
N38522: D17.2(ANODE) R15.2
N38634: D18.2(ANODE) R16.2
N38702: J4.1(P1) U6.3(I-) U6.4(I-.)
N38762: J5.1(P1) U7.3(I-) U7.4(I-.)
N41110: C50.1 U6.6(Filter)
N41352: C51.1 U7.6(Filter)
N42617: D1.2 J2.1(P1) J6.1
N48243: C62.2 R35.2 R37.2 U16.3(+IN)
N48256: R35.1 U20.7(Vout+)
N48260: R36.1 U20.6(Vout-)
N48264: C61.1 R36.2 R38.1 U16.2(-IN)
N48807: C58.1 R33.2 R39.1 U20.2(Vin)
N51115: C67.2 R41.2 R43.2 U16.5(+IN)
N51119: R41.1 U21.7(Vout+)
N51123: R42.1 U21.6(Vout-)
N51127: C66.1 R42.2 R44.1 U16.6(-IN)
N51293: C63.1 R40.2 R45.1 U21.2(Vin)
N52251: C72.2 R47.2 R49.2 U16.10(+IN)
N52255: R47.1 U22.7(Vout+)
N52259: R48.1 U22.6(Vout-)
N52263: C71.1 R48.2 R50.1 U16.9(-IN)
N52425: C68.1 R46.2 R51.1 U22.2(Vin)
N53429: C77.2 R53.2 R55.2 U16.12(+IN)
N53433: R53.1 U23.7(Vout+)
N53437: R54.1 U23.6(Vout-)
N53441: C76.1 R54.2 R56.1 U16.13(-IN)
N53579: C73.1 R52.2 R57.1 U23.2(Vin)
N54653: C82.2 R59.2 R61.2 U17.3(+IN)
N54657: R59.1 U24.7(Vout+)
N54661: R60.1 U24.6(Vout-)
N54665: C81.1 R60.2 R62.1 U17.2(-IN)
N54807: C78.1 R58.2 R63.1 U24.2(Vin)
N56809: C87.2 R65.2 R67.2 U17.5(+IN)
N56813: R65.1 U25.7(Vout+)
N56817: R66.1 U25.6(Vout-)
N56821: C86.1 R66.2 R68.1 U17.6(-IN)
N56959: C83.1 R64.2 R69.1 U25.2(Vin)
N58569: C88.1 R70.2 R71.1 U17.10(+IN)
N59411: C89.1 R72.2 R73.1 U17.12(+IN)
N71004: ADC1.7(REF_IN) C102.2 R75.2 U27.6(V+.) U27.8(V+)
N126025: D19.2(ANODE) R80.2
N126027: D25.2(ANODE) R86.2
N126029: D24.2(ANODE) R85.2
N126031: D23.2(ANODE) R84.2
N126033: D22.2(ANODE) R83.2
N126035: D26.2(ANODE) R87.2
N126037: D21.2(ANODE) R82.2
N126039: D20.2(ANODE) R81.2
N179536: R17.2 U8.2(AN)
N179562: R88.1 U8.6(V_OUT) U8.7(V_OUT.)
N179712: R19.2 U9.2(AN)
N179754: R90.1 U9.6(V_OUT) U9.7(V_OUT.)
N179920: R21.2 U10.2(AN)
N179946: R92.1 U10.6(V_OUT) U10.7(V_OUT.)
N180096: R23.2 U11.2(AN)
N180138: R24.1 U11.6(V_OUT) U11.7(V_OUT.)
N180288: R25.2 U12.2(AN)
N180330: R89.1 U12.6(V_OUT) U12.7(V_OUT.)
N180476: R27.2 U13.2(AN)
N180502: R91.1 U13.6(V_OUT) U13.7(V_OUT.)
N180632: R29.2 U14.2(AN)
N180674: R93.1 U14.6(V_OUT) U14.7(V_OUT.)
N180804: R31.2 U15.2(AN)
N180846: R32.1 U15.6(V_OUT) U15.7(V_OUT.)
N223775: C105.1 U30.6(Filter)
N223929: L5.1 U30.3(I-) U30.4(I-.)
N248745: C108.1 U31.6(Filter)
N249090: L4.1 U31.3(I-) U31.4(I-.)

Not connected (* = marked no-connect by the designer): J1 19* 39*; J6 3*; MECH1 1*; MECH2 1*; MECH3 1*; MECH4 1*; PM1 3(On/Off)* 5(NC.)* 8(NC..)*; PM2 3(On/Off)* 5(NC.)* 8(NC..)*; PM3 3(On/Off)* 5(NC.)* 8(NC..)*; PM4 3(On/Off)* 5(NC.)* 8(NC..)*; U3 2(NC1)* 4(NC2)* 13(NC3)* 15(NC4)*; U8 1(NC)* 4(NC.)*; U9 1(NC)* 4(NC.)*; U10 1(NC)* 4(NC.)*; U11 1(NC)* 4(NC.)*; U12 1(NC)* 4(NC.)*; U13 1(NC)* 4(NC.)*; U14 1(NC)* 4(NC.)*; U15 1(NC)* 4(NC.)*; U27 1(NC)* 2(NC.)* 3(NC..)* 5(ADJ)* 7(NC...)*

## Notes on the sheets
sheet 1
- Isolated Voltage Sensing
- OpAmp Power
- SCR Upper Isolated Supply
- Scale : (R39, R45, R51, R57, R63, and R69)
  66V   = 2V for 31.6k Resistor (RK73H1JTTD3162F)
  400V = 2V for 4.99k Resistor (RK73H1JTTD4991D)
  +/-66V   = 2V for 13.7k Resistor (RK73H1JTTD1372F)
- Voltage Scaling for DSP ADC
- Scale : 5V = 3V
  fc = 72.3 kHz
- Isolated 3.3V/5V Supplies
- Scale : 5V = 3V
  fc = 72.3 kHz
- SPI ADC - 5V Input, 3.3V I/O
- DSP Connection
- External Interface
- Status LEDs
- Vin to Isolated Gate Voltage Converter
- GPIO-20 thru GPIO-23:
  May be configured as encoder input.
- DSP_G2 and DSP_G4:
  Are may be used as general I/O or PWM Outputs.
- Pot Interface
sheet 2
- DC Power Entry (9V-36V)
- Buck Output
  Interconnect
- SCR Drivers
- High-Side
- Low-Side
- Buck Converter 1 (50V Max)
- Buck Converter 2 (50V Max)
- IGBT Drivers (Buck Converters)
- 3-Phase Converter (SCR)
- TestPoints
- Current
- SCR Notes:
  SJ6020RTP- (Gate Resistors = 470 Ohm)
  35 mA Gate Trigger and 75 mA Holding Current Max
  SJ6020R2TP- (Gate Resistors = 1k Ohm)
  10 mA Gate Trigger and 35 mA Holding Current Max
- Voltage
- Mounting
